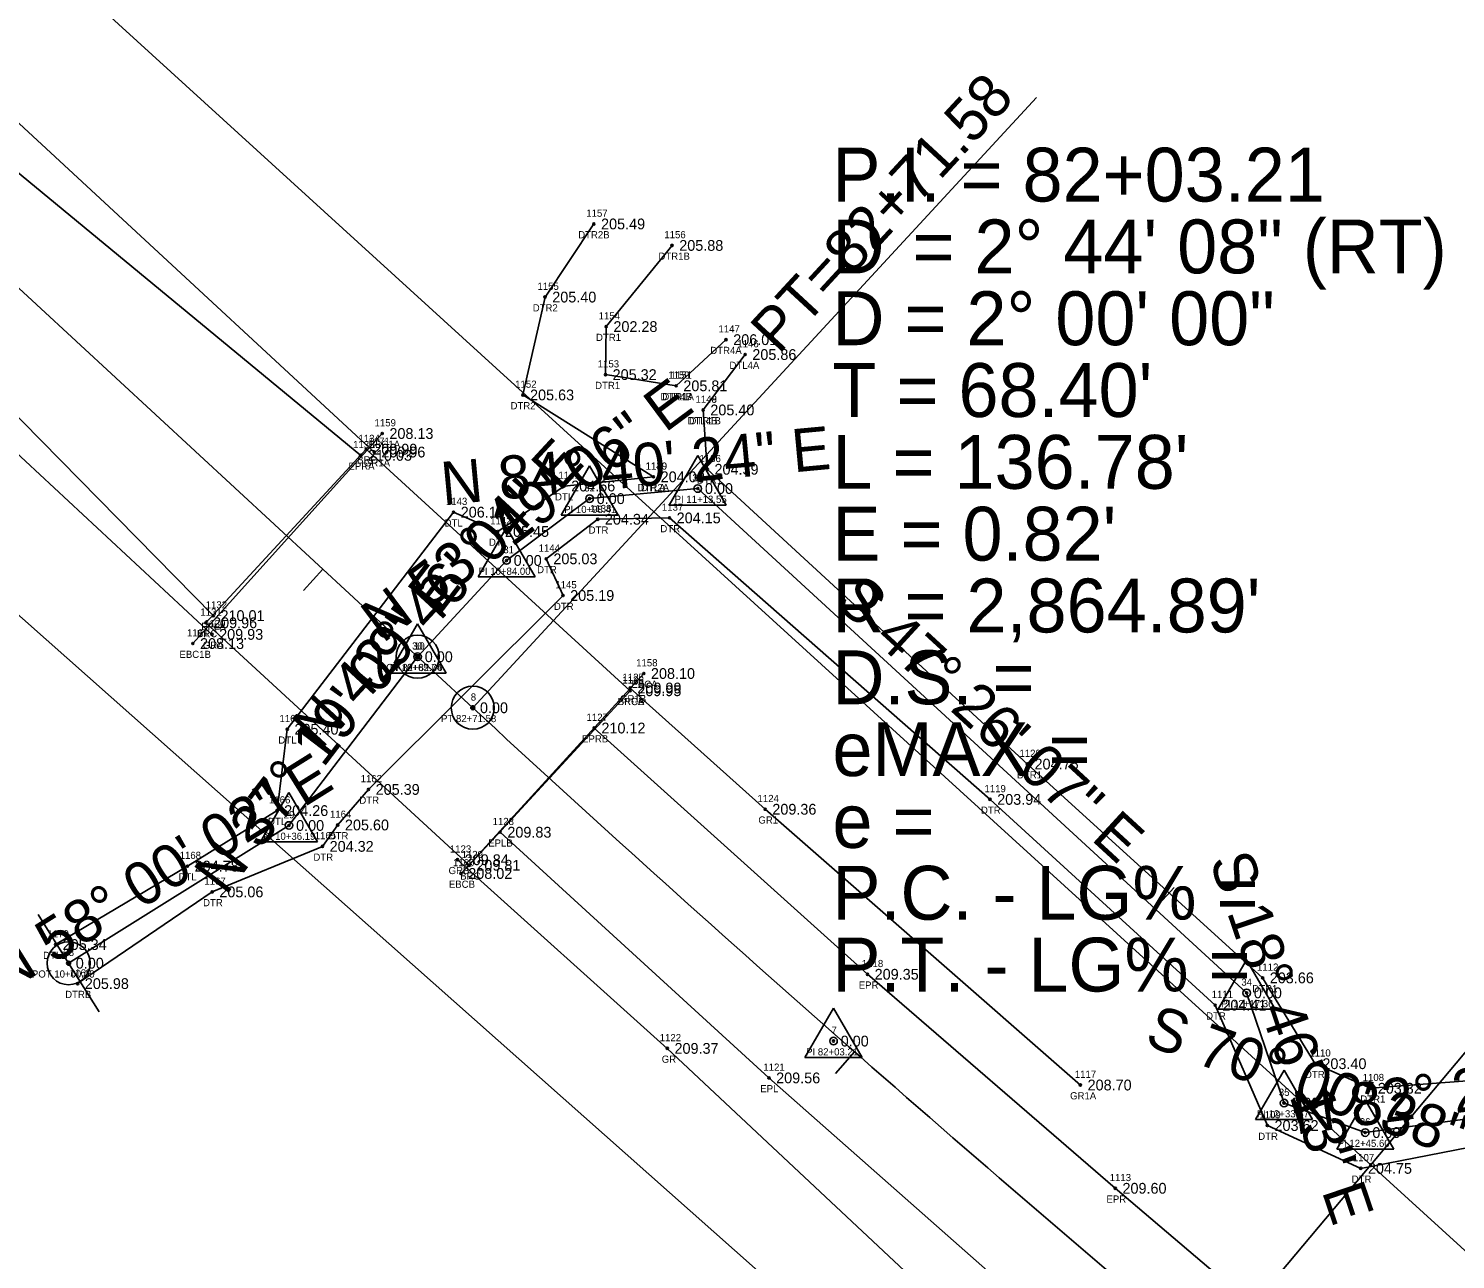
# Model space of a CAD drawing. Extents: x 2259948 to 2261336, y 1064647 to 1065986.
# Drawn here: x 2260425 to 2260623.8, y 1065276.7 to 1065448.1 of the extents above; entities that cross this region are included whole.
import ezdxf

# ---------------------------------------------------------------- set-up
doc = ezdxf.new("R2010")
doc.units = 0
for name, color, linetype in [('RD_EX_Bridge', 7, 'Continuous'), ('RD_EX_Bridge_txCode', 7, 'Continuous'), ('RD_EX_GuardRail', 7, 'Continuous'), ('RD_EX_GuardRail_txCode', 7, 'Continuous'), ('RD_EX_H2O', 7, 'Continuous'), ('RD_EX_H2O_txCode', 7, 'Continuous'), ('RD_EX_Road', 7, 'Continuous'), ('RD_EX_Road_txCode', 7, 'Continuous'), ('RD_EX_TX_Bridge_ELEV', 7, 'Continuous'), ('RD_EX_TX_GuardRail_ELEV', 7, 'Continuous'), ('RD_EX_TX_H2O_ELEV', 7, 'Continuous'), ('RD_EX_TX_Road_ELEV', 7, 'Continuous'), ('RD_EX_VEG', 7, 'Continuous'), ('RD_HC_Cl', 7, 'Continuous'), ('RD_HC_Data', 7, 'Continuous'), ('RD_HC_Data_Tic', 7, 'Continuous'), ('RD_HC_Survey_ELEV', 7, 'Continuous'), ('RD_HC_txCode', 7, 'Continuous'), ('RD_SMD_Locator', 7, 'Continuous')]:
    doc.layers.add(name, color=color, linetype=linetype)

msp = doc.modelspace()

# ---------------------------------------------------------------- linework, layer by layer
at = {"layer": 'RD_EX_Bridge'}
for p, q in [((2260474.29, 1065391.7), (2260447.91, 1065362.45)), ((2260510.72, 1065358.28), (2260485.27, 1065330.44))]:
    msp.add_line(p, q, dxfattribs=at)
msp.add_lwpolyline([(2260508.82, 1065355.88), (2260486.4, 1065331.58), (2260449.73, 1065365.34), (2260472.04, 1065389.52), (2260508.82, 1065355.88)], dxfattribs=at)
at = {"layer": 'RD_EX_GuardRail'}
for p, q in [((2260473.16, 1065389.12), (2260411.07, 1065446.52)), ((2260450.57, 1065363.73), (2260388.28, 1065421.56))]:
    msp.add_line(p, q, dxfattribs=at)
for points in [[(2260571.54, 1065300.98), (2260527.63, 1065339.38), (2260508.83, 1065356.26)], [(2260547.78, 1065274.39), (2260514, 1065306.08), (2260484.78, 1065332.35)]]:
    msp.add_lwpolyline(points, dxfattribs=at)
at = {"layer": 'RD_EX_H2O'}
for p, q in [((2260522.18, 1065404.77), (2260515.23, 1065398.34)), ((2260524.84, 1065402.7), (2260518.99, 1065394.98))]:
    msp.add_line(p, q, dxfattribs=at)
for points in [[(2260512.07, 1065385.67), (2260493.88, 1065397.07), (2260496.97, 1065410.7), (2260503.77, 1065420.88)], [(2260515.23, 1065398.34), (2260505.38, 1065399.9), (2260505.49, 1065406.59), (2260514.66, 1065417.89)], [(2260649.32, 1065303.35), (2260611.96, 1065300.53), (2260604.25, 1065303.95), (2260596.92, 1065315.9), (2260564.15, 1065345.67), (2260519.57, 1065386.72), (2260518.99, 1065394.98)], [(2260512.07, 1065385.67), (2260499.61, 1065384.39), (2260490.39, 1065378.06), (2260484.22, 1065380.75), (2260461.06, 1065350.52), (2260459.63, 1065339.19), (2260447.16, 1065331.46), (2260428.77, 1065320.54)], [(2260646.56, 1065296.38), (2260610.59, 1065289.37), (2260597.58, 1065295.34), (2260590.32, 1065312.1), (2260558.95, 1065340.75), (2260514.3, 1065379.95), (2260504.3, 1065379.76), (2260497.13, 1065374.25), (2260499.47, 1065369.14), (2260472.37, 1065342.14), (2260468.09, 1065337.19), (2260465.96, 1065334.21), (2260450.6, 1065327.87), (2260431.86, 1065315.1)]]:
    msp.add_lwpolyline(points, dxfattribs=at)
at = {"layer": 'RD_EX_Road'}
for points in [[(2260471.29, 1065388.66), (2260408.54, 1065440.4), (2260398.69, 1065449.49), (2260347.1, 1065496.93), (2260329.06, 1065513.35), (2260281.81, 1065556.62)], [(2260450.76, 1065366.34), (2260384.25, 1065433.92), (2260316.12, 1065498), (2260269.16, 1065540.98)], [(2260785.94, 1065112.1), (2260748.83, 1065143.25), (2260679.89, 1065200.15), (2260614.93, 1065253.84), (2260576.4, 1065286.6), (2260541.88, 1065316.4), (2260503.82, 1065350.69)], [(2260773.44, 1065097.37), (2260736.13, 1065128.07), (2260602.8, 1065238.77), (2260563.77, 1065270.54), (2260528.16, 1065301.97), (2260490.72, 1065336.18)]]:
    msp.add_lwpolyline(points, dxfattribs=at)
at = {"layer": 'RD_EX_VEG'}
for points in [[(2261134.31, 1064842.95), (2260842.2, 1065097.67), (2260806.91, 1065126.77), (2260758.4, 1065156.57), (2260401.57, 1065481.47), (2260414.95, 1065532.7)], [(2261105.29, 1064796.67), (2260883, 1064984.96), (2260766.14, 1065062.68), (2260367.33, 1065416.28), (2260257.33, 1065527.76)]]:
    msp.add_lwpolyline(points, dxfattribs=at)
at = {"layer": 'RD_HC_Cl'}
for p, q in [((2260486.9, 1065353.51), (2260275.49, 1065548.81)), ((2260503.16, 1065382.63), (2260518.24, 1065384.04)), ((2260518.24, 1065384.04), (2260594.7, 1065313.81)), ((2260491.6, 1065374.02), (2260503.16, 1065382.63)), ((2260479.21, 1065360.62), (2260491.6, 1065374.02)), ((2260461.29, 1065337.12), (2260479.21, 1065360.62)), ((2260430.6, 1065317.94), (2260461.29, 1065337.12)), ((2260594.7, 1065313.81), (2260599.91, 1065298.47)), ((2260599.91, 1065298.47), (2260611.21, 1065294.36)), ((2260611.21, 1065294.36), (2260647.64, 1065299.24))]:
    msp.add_line(p, q, dxfattribs=at)
msp.add_arc((2262430.9, 1067457.9), 2864.89, 227.26888, 230.00433, dxfattribs=at)
at = {"layer": 'RD_HC_Data'}
for p, q in [((2260486.9, 1065353.51), (2260565.42, 1065438.51)), ((2260499.19, 1065380.34), (2260503.17, 1065387.22)), ((2260503.17, 1065387.22), (2260507.13, 1065380.34)), ((2260514.27, 1065381.74), (2260518.24, 1065388.62)), ((2260518.24, 1065388.62), (2260522.21, 1065381.74)), ((2260514.27, 1065381.74), (2260522.21, 1065381.74)), ((2260499.19, 1065380.34), (2260507.13, 1065380.34)), ((2260487.63, 1065371.72), (2260491.6, 1065378.6)), ((2260491.6, 1065378.6), (2260495.57, 1065371.72)), ((2260487.63, 1065371.72), (2260495.57, 1065371.72)), ((2260475.24, 1065358.32), (2260479.21, 1065365.2)), ((2260479.21, 1065365.2), (2260483.18, 1065358.32)), ((2260475.24, 1065358.32), (2260483.18, 1065358.32)), ((2260589.55, 1065263.13), (2260664.14, 1065352.04)), ((2260457.32, 1065334.83), (2260461.29, 1065341.7)), ((2260461.29, 1065341.7), (2260465.26, 1065334.83)), ((2260457.32, 1065334.83), (2260465.26, 1065334.83)), ((2260590.72, 1065311.52), (2260594.7, 1065318.4)), ((2260594.7, 1065318.4), (2260598.67, 1065311.52)), ((2260533.17, 1065304.8), (2260537.15, 1065311.68)), ((2260537.15, 1065311.68), (2260541.12, 1065304.8)), ((2260590.72, 1065311.52), (2260598.67, 1065311.52)), ((2260533.17, 1065304.8), (2260541.12, 1065304.8)), ((2260595.94, 1065296.17), (2260599.91, 1065303.05)), ((2260599.91, 1065303.05), (2260603.88, 1065296.17)), ((2260607.24, 1065292.06), (2260611.21, 1065298.94)), ((2260611.21, 1065298.94), (2260615.18, 1065292.06)), ((2260595.94, 1065296.17), (2260603.88, 1065296.17)), ((2260607.24, 1065292.06), (2260615.18, 1065292.06))]:
    msp.add_line(p, q, dxfattribs=at)
for centre, radius in [((2260503.16, 1065382.63), 0.529), ((2260518.24, 1065384.04), 0.529), ((2260491.6, 1065374.02), 0.529), ((2260479.21, 1065360.62), 3), ((2260479.21, 1065360.62), 0.529), ((2260479.21, 1065360.62), 0.282), ((2260486.9, 1065353.51), 3), ((2260486.9, 1065353.51), 0.282), ((2260461.29, 1065337.12), 0.529), ((2260430.6, 1065317.94), 3), ((2260430.6, 1065317.94), 0.282), ((2260594.7, 1065313.81), 0.529), ((2260537.15, 1065307.1), 0.529), ((2260599.91, 1065298.47), 0.529), ((2260611.21, 1065294.36), 0.529)]:
    msp.add_circle(centre, radius, dxfattribs=at)
at = {"layer": 'RD_HC_Data_Tic'}
for p, q in [((2260504.74, 1065382.78), (2260504.37, 1065386.76)), ((2260466.03, 1065372.79), (2260463.31, 1065369.85)), ((2260581.91, 1065325.56), (2260584.61, 1065328.5)), ((2260430.6, 1065317.94), (2260426.36, 1065324.72)), ((2260430.6, 1065317.94), (2260434.84, 1065311.15)), ((2260540.08, 1065305.6), (2260537.44, 1065302.59))]:
    msp.add_line(p, q, dxfattribs=at)
at = {"layer": 'RD_SMD_Locator'}
for centre in [(2260503.77, 1065420.88), (2260514.66, 1065417.89), (2260496.97, 1065410.7), (2260505.49, 1065406.59), (2260522.18, 1065404.77), (2260524.84, 1065402.7), (2260505.38, 1065399.9), (2260493.88, 1065397.07), (2260515.23, 1065398.34), (2260515.23, 1065398.34), (2260518.99, 1065394.98), (2260518.99, 1065394.98), (2260474.29, 1065391.7), (2260472.04, 1065389.52), (2260473.16, 1065389.12), (2260471.29, 1065388.66), (2260512.07, 1065385.67), (2260512.07, 1065385.67), (2260519.57, 1065386.72), (2260499.61, 1065384.39), (2260518.24, 1065384.04), (2260503.16, 1065382.63), (2260484.22, 1065380.75), (2260504.3, 1065379.76), (2260514.3, 1065379.95), (2260490.39, 1065378.06), (2260491.6, 1065374.02), (2260497.13, 1065374.25), (2260499.47, 1065369.14), (2260449.73, 1065365.34), (2260450.76, 1065366.34), (2260450.57, 1065363.73), (2260447.91, 1065362.45), (2260479.21, 1065360.62), (2260479.21, 1065360.62), (2260510.72, 1065358.28), (2260508.82, 1065355.88), (2260508.82, 1065355.88), (2260508.83, 1065356.26), (2260486.9, 1065353.51), (2260461.06, 1065350.52), (2260503.82, 1065350.69), (2260564.15, 1065345.67), (2260472.37, 1065342.14), (2260459.63, 1065339.19), (2260527.63, 1065339.38), (2260558.95, 1065340.75), (2260468.09, 1065337.19), (2260461.29, 1065337.12), (2260490.72, 1065336.18), (2260465.96, 1065334.21), (2260447.16, 1065331.46), (2260484.78, 1065332.35), (2260486.4, 1065331.58), (2260485.27, 1065330.44), (2260450.6, 1065327.87), (2260428.77, 1065320.54), (2260430.6, 1065317.94), (2260541.88, 1065316.4), (2260596.92, 1065315.9), (2260431.86, 1065315.1), (2260594.7, 1065313.81), (2260590.32, 1065312.1), (2260514, 1065306.08), (2260537.15, 1065307.1), (2260604.25, 1065303.95), (2260528.16, 1065301.97), (2260571.54, 1065300.98), (2260611.96, 1065300.53), (2260599.91, 1065298.47), (2260597.58, 1065295.34), (2260611.21, 1065294.36), (2260610.59, 1065289.37), (2260576.4, 1065286.6)]:
    msp.add_circle(centre, 0.15, dxfattribs=at)

# ---------------------------------------------------------------- texts
at = {"layer": 'RD_EX_Bridge_txCode'}
for s, p in [('1159', (2260473.22, 1065392.7)), ('1134', (2260470.98, 1065390.52)), ('EBC1A', (2260472.4, 1065389.7)), ('BRC', (2260470.79, 1065387.52)), ('1131', (2260448.95, 1065366.34)), ('1161', (2260447.1, 1065363.45)), ('BRC', (2260448.48, 1065363.34)), ('EBC1B', (2260446.04, 1065360.45)), ('1158', (2260509.66, 1065359.28)), ('1126', (2260507.73, 1065356.88)), ('1135', (2260507.76, 1065356.88)), ('EBCA', (2260509, 1065356.28)), ('BRCA', (2260507.08, 1065353.88)), ('BRCB', (2260507.1, 1065353.88)), ('1129', (2260485.34, 1065332.58)), ('1160', (2260484.14, 1065331.44)), ('EBCB', (2260483.57, 1065328.44)), ('BRC', (2260485.15, 1065329.58))]:
    msp.add_text(s, height=1, dxfattribs=at).set_placement(p)
at = {"layer": 'RD_EX_GuardRail_txCode'}
for s, p in [('1171', (2260472.38, 1065390.12)), ('GR1A', (2260471.73, 1065387.12)), ('1130', (2260449.46, 1065364.73)), ('GRA', (2260449.3, 1065361.73)), ('1125', (2260507.76, 1065357.26)), ('GR1B', (2260507.41, 1065354.26)), ('1124', (2260526.57, 1065340.38)), ('GR1', (2260526.68, 1065337.38)), ('1123', (2260483.71, 1065333.35)), ('GRB', (2260483.53, 1065330.35)), ('1122', (2260512.94, 1065307.08)), ('GR', (2260513.22, 1065304.08)), ('1117', (2260570.76, 1065301.98)), ('GR1A', (2260570.1, 1065298.98))]:
    msp.add_text(s, height=1, dxfattribs=at).set_placement(p)
at = {"layer": 'RD_EX_H2O_txCode'}
for s, p in [('1157', (2260502.71, 1065421.88)), ('DTR2B', (2260501.58, 1065418.88)), ('1156', (2260513.58, 1065418.89)), ('DTR1B', (2260512.76, 1065415.89)), ('1155', (2260495.91, 1065411.7)), ('DTR2', (2260495.25, 1065408.7)), ('1154', (2260504.43, 1065407.59)), ('DTR1', (2260504.06, 1065404.59)), ('1147', (2260521.12, 1065405.77)), ('DTR4A', (2260519.98, 1065402.77)), ('1146', (2260523.75, 1065403.7)), ('1153', (2260504.31, 1065400.9)), ('DTL4A', (2260522.65, 1065400.7)), ('1152', (2260492.81, 1065398.07)), ('1150', (2260514.13, 1065399.34)), ('1151', (2260514.45, 1065399.34)), ('DTR1', (2260503.94, 1065397.9)), ('DTR4B', (2260513.04, 1065396.34)), ('DTR1A', (2260513.31, 1065396.34)), ('1148', (2260517.93, 1065395.98)), ('1149', (2260517.93, 1065395.98)), ('DTR2', (2260492.16, 1065395.07)), ('DTL4B', (2260516.82, 1065392.98)), ('DTR1B', (2260517.08, 1065392.98)), ('1140', (2260510.96, 1065386.67)), ('1139', (2260511, 1065386.67)), ('1136', (2260518.48, 1065387.72)), ('1141', (2260498.83, 1065385.39)), ('DTR1', (2260518.14, 1065384.72)), ('DTL', (2260498.36, 1065382.39)), ('DTR2A', (2260509.86, 1065383.67)), ('DTLA', (2260510.33, 1065383.67)), ('1143', (2260483.16, 1065381.75)), ('1138', (2260503.24, 1065380.76)), ('1137', (2260513.24, 1065380.95)), ('DTL', (2260482.98, 1065378.75)), ('1142', (2260489.33, 1065379.06)), ('DTR', (2260503.04, 1065377.76)), ('DTR', (2260513.03, 1065377.95)), ('DTL', (2260489.15, 1065376.06)), ('1144', (2260496.07, 1065375.25)), ('DTR', (2260495.86, 1065372.25)), ('1145', (2260498.4, 1065370.14)), ('DTR', (2260498.2, 1065367.14)), ('1163', (2260459.98, 1065351.52)), ('DTL', (2260459.82, 1065348.52)), ('1120', (2260563.05, 1065346.67)), ('1162', (2260471.28, 1065343.14)), ('DTR1', (2260562.71, 1065343.67)), ('1119', (2260558.18, 1065341.75)), ('1166', (2260458.52, 1065340.19)), ('DTR', (2260471.1, 1065340.14)), ('DTR', (2260557.69, 1065338.75)), ('DTL', (2260458.38, 1065337.19)), ('1164', (2260467.01, 1065338.19)), ('1165', (2260464.88, 1065335.21)), ('DTR', (2260466.82, 1065335.19)), ('1168', (2260446.07, 1065332.46)), ('DTR', (2260464.7, 1065332.21)), ('DTL', (2260445.92, 1065329.46)), ('1167', (2260449.51, 1065328.87)), ('DTR', (2260449.33, 1065325.87)), ('1170', (2260427.66, 1065321.54)), ('DTLB', (2260427.05, 1065318.54)), ('1112', (2260596.14, 1065316.9)), ('1169', (2260430.78, 1065316.1)), ('DTRB', (2260430.12, 1065313.1)), ('1111', (2260589.83, 1065313.1)), ('DTR1', (2260595.49, 1065313.9)), ('DTR', (2260589.05, 1065310.1)), ('1110', (2260603.43, 1065304.95)), ('DTR1', (2260602.82, 1065301.95)), ('1108', (2260610.86, 1065301.53)), ('DTR1', (2260610.53, 1065298.53)), ('1109', (2260596.47, 1065296.34)), ('DTR', (2260596.31, 1065293.34)), ('1107', (2260609.49, 1065290.37)), ('DTR', (2260609.33, 1065287.37))]:
    msp.add_text(s, height=1, dxfattribs=at).set_placement(p)
at = {"layer": 'RD_EX_Road_txCode'}
for s, p in [('1133', (2260470.23, 1065389.66)), ('EPRA', (2260469.58, 1065386.66)), ('1132', (2260449.7, 1065367.34)), ('EPLA', (2260449.07, 1065364.34)), ('1127', (2260502.75, 1065351.69)), ('EPRB', (2260502.12, 1065348.69)), ('1128', (2260489.66, 1065337.18)), ('EPLB', (2260489.05, 1065334.18)), ('1118', (2260541.1, 1065317.4)), ('EPR', (2260540.66, 1065314.4)), ('1121', (2260527.38, 1065302.97)), ('EPL', (2260526.95, 1065299.97)), ('1113', (2260575.62, 1065287.6)), ('EPR', (2260575.17, 1065284.6))]:
    msp.add_text(s, height=1, dxfattribs=at).set_placement(p)
at = {"layer": 'RD_EX_TX_Bridge_ELEV'}
for s, p in [('208.13', (2260475.29, 1065390.95)), ('209.99', (2260473.04, 1065388.77)), ('209.96', (2260450.73, 1065364.59)), ('208.13', (2260448.91, 1065361.7)), ('208.10', (2260511.72, 1065357.53)), ('209.95', (2260509.82, 1065355.13)), ('209.95', (2260509.82, 1065355.13)), ('209.81', (2260487.4, 1065330.83)), ('208.02', (2260486.27, 1065329.69))]:
    msp.add_text(s, height=1.5, dxfattribs=at).set_placement(p)
at = {"layer": 'RD_EX_TX_GuardRail_ELEV'}
for s, p in [('209.96', (2260474.16, 1065388.37)), ('209.93', (2260451.57, 1065362.98)), ('209.99', (2260509.83, 1065355.51)), ('209.36', (2260528.63, 1065338.63)), ('209.84', (2260485.78, 1065331.6)), ('209.37', (2260515, 1065305.33)), ('208.70', (2260572.54, 1065300.23))]:
    msp.add_text(s, height=1.5, dxfattribs=at).set_placement(p)
at = {"layer": 'RD_EX_TX_H2O_ELEV'}
for s, p in [('205.49', (2260504.77, 1065420.13)), ('205.88', (2260515.66, 1065417.14)), ('205.40', (2260497.97, 1065409.95)), ('202.28', (2260506.49, 1065405.84)), ('206.01', (2260523.18, 1065404.02)), ('205.86', (2260525.84, 1065401.95)), ('205.32', (2260506.38, 1065399.15)), ('205.81', (2260516.23, 1065397.59)), ('205.81', (2260516.23, 1065397.59)), ('205.63', (2260494.88, 1065396.32)), ('205.40', (2260519.99, 1065394.23)), ('205.40', (2260519.99, 1065394.23)), ('204.39', (2260520.57, 1065385.97)), ('204.66', (2260500.61, 1065383.64)), ('204.00', (2260513.07, 1065384.92)), ('204.00', (2260513.07, 1065384.92)), ('206.15', (2260485.22, 1065380)), ('204.34', (2260505.3, 1065379.01)), ('204.15', (2260515.3, 1065379.2)), ('205.45', (2260491.39, 1065377.31)), ('205.03', (2260498.13, 1065373.5)), ('205.19', (2260500.47, 1065368.39)), ('205.40', (2260462.06, 1065349.77)), ('204.75', (2260565.15, 1065344.92)), ('205.39', (2260473.37, 1065341.39)), ('203.94', (2260559.95, 1065340)), ('204.26', (2260460.63, 1065338.44)), ('205.60', (2260469.09, 1065336.44)), ('204.32', (2260466.96, 1065333.46)), ('204.78', (2260448.16, 1065330.71)), ('205.06', (2260451.6, 1065327.12)), ('205.34', (2260429.77, 1065319.79)), ('205.98', (2260432.86, 1065314.35)), ('203.66', (2260597.92, 1065315.15)), ('204.41', (2260591.32, 1065311.35)), ('203.40', (2260605.25, 1065303.2)), ('203.32', (2260612.96, 1065299.78)), ('203.62', (2260598.58, 1065294.59)), ('204.75', (2260611.59, 1065288.62))]:
    msp.add_text(s, height=1.5, dxfattribs=at).set_placement(p)
at = {"layer": 'RD_EX_TX_Road_ELEV'}
for s, p in [('210.03', (2260472.29, 1065387.91)), ('210.01', (2260451.76, 1065365.59)), ('210.12', (2260504.82, 1065349.94)), ('209.83', (2260491.72, 1065335.43)), ('209.35', (2260542.88, 1065315.65)), ('209.56', (2260529.16, 1065301.22)), ('209.60', (2260577.4, 1065285.85))]:
    msp.add_text(s, height=1.5, dxfattribs=at).set_placement(p)
at = {"layer": 'RD_HC_Data'}
for s, rotation, p in [('PT=82+71.58', 47.2689, (2260529.54, 1065402.61)), ('N 53%%d 19\' 06" E', 36.6818, (2260474.35, 1065362.41)), ('N 42%%d 46\' 04" E', 47.2322, (2260465.67, 1065347.46)), ('N 84%%d 40\' 24" E', 5.3267, (2260482.75, 1065381.73)), ('N 37%%d 19\' 09" E', 52.6809, (2260452.49, 1065327.22)), ('S 47%%d 26\' 07" E', 317.4354, (2260537.08, 1065368.09)), ('N 58%%d 00\' 02" E', 31.9995, (2260421.69, 1065313.55)), ('S 18%%d 46\' 13" E', 288.7702, (2260589.48, 1065332.26)), ('S 70%%d 00\' 38" E', 340.0104, (2260580.3, 1065306.66)), ('N 82%%d 21\' 55" E', 7.6347, (2260601.56, 1065294.07))]:
    msp.add_text(s, height=6, rotation=rotation, dxfattribs=at).set_placement(p)
for s, p in [('P.I. = 82+03.21', (2260537, 1065424)), ('D', (2260537, 1065414)), ('    = 2%%d 44\' 08" (RT)', (2260537, 1065414)), ('D = 2%%d 00\' 00"', (2260537, 1065404)), ("T = 68.40'", (2260537, 1065394)), ("L = 136.78'", (2260537, 1065384)), ("E = 0.82'", (2260537, 1065374)), ("R = 2,864.89'", (2260537, 1065364)), ('D.S. = ', (2260537, 1065354)), ('eMAX = ', (2260537, 1065344)), ('e = ', (2260537, 1065334)), ('P.C. - LG% = ', (2260537, 1065324)), ('P.T. - LG% = ', (2260537, 1065314))]:
    msp.add_text(s, height=7.5, dxfattribs=at).set_placement(p)
at = {"layer": 'RD_HC_Survey_ELEV'}
for p in [(2260504.16, 1065381.88), (2260519.24, 1065383.29), (2260492.6, 1065373.27), (2260480.21, 1065359.87), (2260480.21, 1065359.87), (2260487.9, 1065352.76), (2260462.29, 1065336.37), (2260431.6, 1065317.19), (2260595.7, 1065313.06), (2260538.15, 1065306.35), (2260600.91, 1065297.72), (2260612.21, 1065293.61)]:
    msp.add_text('0.00', height=1.5, dxfattribs=at).set_placement(p)
at = {"layer": 'RD_HC_txCode'}
for s, p in [('33', (2260517.5, 1065385.04)), ('32', (2260502.43, 1065383.63)), ('PI 11+13.55', (2260515.02, 1065382.04)), ('PI 10+98.41', (2260499.63, 1065380.63)), ('31', (2260491.15, 1065375.02)), ('PI 10+84.00', (2260487.7, 1065372.02)), ('30', (2260478.44, 1065361.62)), ('10', (2260478.72, 1065361.62)), ('POT 82+82.06', (2260473.95, 1065358.62)), ('PI 10+65.74', (2260475.36, 1065358.62)), ('8', (2260486.62, 1065354.51)), ('PT 82+71.58', (2260482.48, 1065351.51)), ('29', (2260460.56, 1065338.12)), ('PI 10+36.19', (2260457.73, 1065335.12)), ('28', (2260429.87, 1065318.94)), ('POT 10+00.00', (2260425.49, 1065315.94)), ('34', (2260593.96, 1065314.81)), ('PI 12+17.36', (2260591.18, 1065311.81)), ('7', (2260536.86, 1065308.1)), ('PI 82+03.21', (2260533.33, 1065305.1)), ('35', (2260599.18, 1065299.47)), ('PI 12+33.57', (2260596.13, 1065296.47)), ('36', (2260610.46, 1065295.36)), ('PI 12+45.60', (2260607.37, 1065292.36))]:
    msp.add_text(s, height=1, dxfattribs=at).set_placement(p)

doc.saveas('drawing.dxf')
